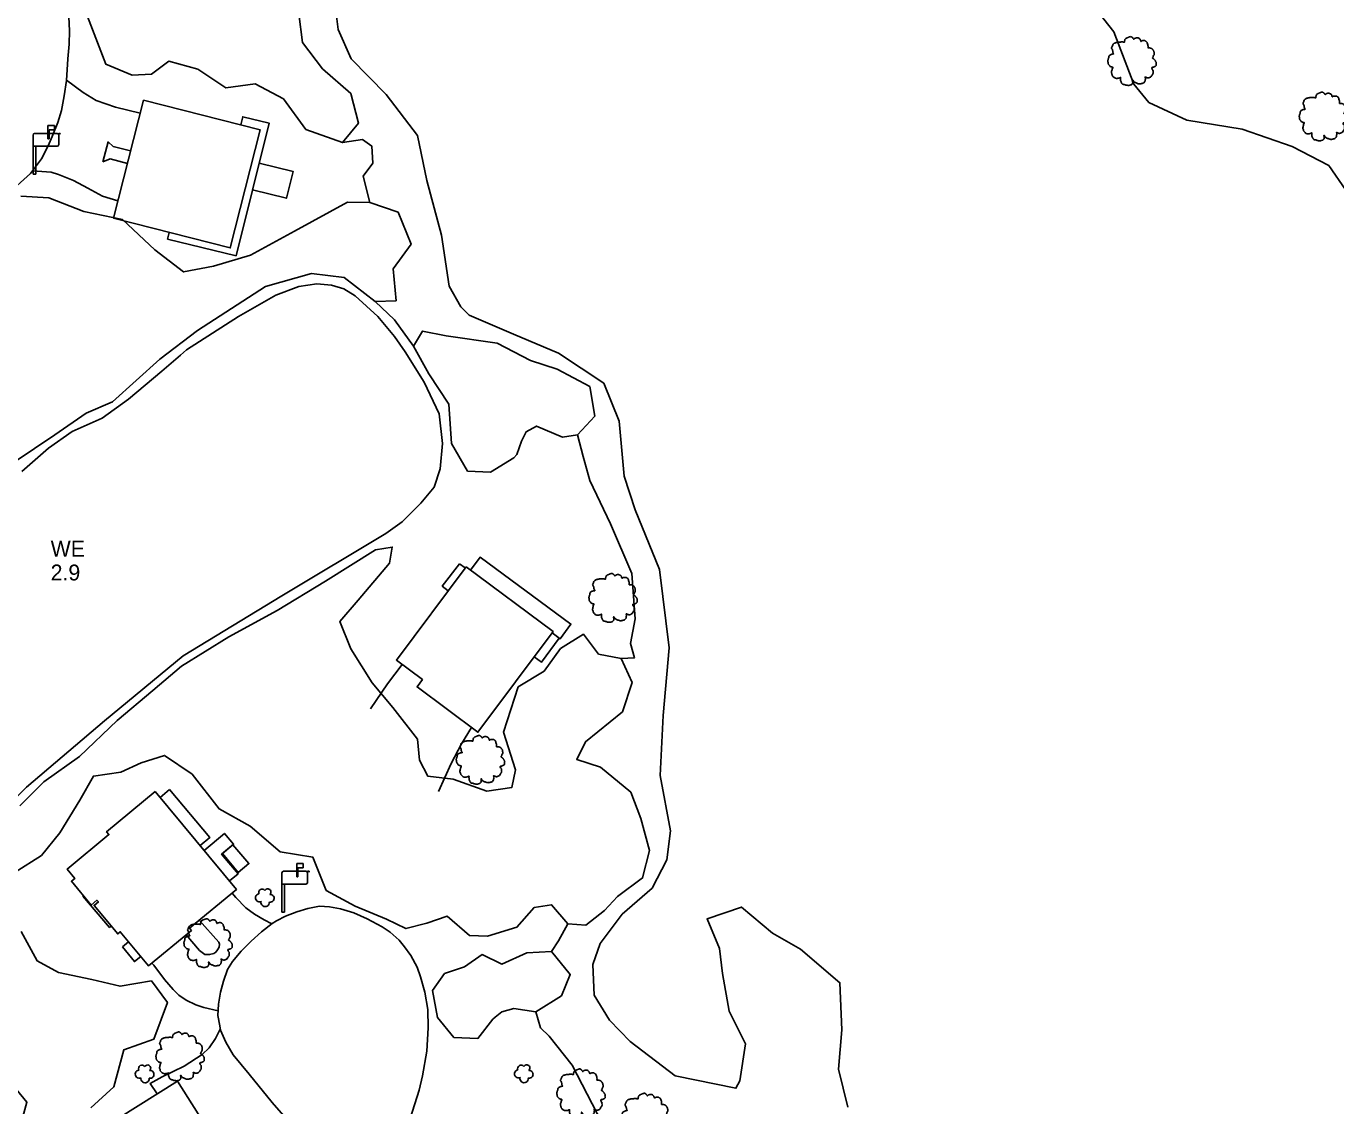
# Model space of a CAD drawing. Extents: x 2160437 to 2172832, y 205694 to 212444.
# Drawn here: x 2171600 to 2172011.7, y 207128.5 to 207468 of the extents above; entities that cross this region are included whole.
import ezdxf

# ---------------------------------------------------------------- set-up
doc = ezdxf.new("R2010")
doc.units = 0
for name, color, linetype in [('RD_EX_Bldg', 7, 'Continuous'), ('RD_EX_Bldg_Walls', 7, 'Continuous'), ('RD_EX_BldgApp', 7, 'Continuous'), ('RD_EX_Driveway', 7, 'Continuous'), ('RD_EX_H2O_Pond', 7, 'Continuous'), ('RD_EX_H2O_txCode', 7, 'Continuous'), ('RD_EX_Road', 7, 'Continuous'), ('RD_EX_VEG', 7, 'Continuous'), ('RD_EX_VEG_ShrubLine', 7, 'Continuous'), ('RD_EX_VEG_TreeLine', 7, 'Continuous')]:
    doc.layers.add(name, color=color, linetype=linetype)

# ---------------------------------------------------------------- blocks, each defined once
blk = doc.blocks.new('T2')
at = {"layer": 'RD_EX_VEG'}
for points in [[(0.05, 7.21), (-0.25, 7.24), (-0.57, 7.14), (-0.82, 7.04), (-1.05, 6.96), (-1.27, 6.86), (-1.57, 6.69), (-1.8, 6.49), (-1.92, 6.24), (-1.97, 6.01), (-2.02, 5.74), (-2.02, 5.56), (-2.15, 5.54), (-2.3, 5.56), (-2.55, 5.64), (-2.8, 5.64), (-3.05, 5.64), (-3.4, 5.61), (-3.75, 5.61), (-4.02, 5.56), (-4.35, 5.51), (-4.72, 5.39), (-5.07, 5.26), (-5.37, 5.01), (-5.62, 4.54), (-5.75, 4.19), (-5.9, 3.94), (-5.75, 3.49), (-5.57, 3.14), (-5.55, 2.94), (-5.47, 2.52), (-5.37, 2.29), (-5.25, 2.09), (-5.32, 2.07), (-5.7, 2.02), (-6, 1.92), (-6.42, 1.69), (-6.64, 1.47), (-6.74, 1.14), (-6.77, 0.79), (-6.87, 0.59), (-6.94, 0.32), (-6.97, 0.24), (-7.02, -0.08), (-6.92, -0.53), (-6.89, -0.88), (-6.77, -1.11), (-6.62, -1.28), (-6.44, -1.53), (-6.05, -1.76), (-5.72, -1.86), (-5.52, -1.88), (-5.7, -2.38), (-5.75, -2.73), (-5.87, -3.13), (-5.87, -3.21), (-5.92, -3.68), (-5.77, -4.01), (-5.7, -4.38), (-5.52, -4.61), (-5.25, -4.91), (-4.92, -5.13), (-4.42, -5.26), (-4.02, -5.23), (-3.45, -5.06), (-3.2, -4.98), (-3.22, -5.16), (-3.2, -5.53), (-3.2, -5.96), (-3.05, -6.28), (-2.95, -6.56), (-2.8, -6.81), (-2.47, -7.03), (-2.07, -7.11), (-1.65, -7.26), (-1.2, -7.33), (-0.7, -7.36), (-0.1, -7.21), (0.18, -7.08), (0.28, -6.91), (0.48, -6.53), (0.43, -6.31), (0.45, -5.71), (0.55, -5.88), (0.73, -6.23), (1.23, -6.53), (1.63, -6.71), (2.1, -6.86), (2.4, -6.93), (2.88, -6.86), (3.25, -6.78), (3.63, -6.66), (3.93, -6.38), (4.1, -6.11), (4.15, -5.83), (4.23, -5.46), (4.28, -5.28)], [(4.28, -5.28), (4.2, -5.11), (4.15, -4.86), (4.23, -4.88), (4.4, -4.93), (4.68, -5.06), (4.9, -5.13), (5.23, -5.11), (5.5, -5.01), (5.95, -4.73), (6.22, -4.26), (6.5, -3.86), (6.57, -3.53), (6.52, -3.31), (6.5, -2.81), (6.3, -2.56), (6.25, -2.43), (6.15, -2.03), (6.22, -1.98), (6.5, -1.93), (6.87, -1.81), (7.15, -1.68), (7.37, -1.51), (7.45, -1.28), (7.42, -0.88), (7.47, -0.48), (7.4, -0.33), (7.3, -0.18), (7.22, 0.02), (7.07, 0.17), (6.97, 0.32), (6.87, 0.42), (6.75, 0.57), (6.57, 0.69), (6.42, 0.74), (6.37, 0.89), (6.52, 1.09), (6.57, 1.19), (6.6, 1.42), (6.82, 1.77), (6.87, 2.17), (6.82, 2.59), (6.77, 2.87), (6.62, 3.14), (6.42, 3.39), (6.3, 3.56), (6.12, 3.69), (5.8, 3.81), (5.55, 3.86), (5.2, 3.86), (5, 3.91), (5.03, 3.96), (5.03, 4.11), (5.03, 4.39), (4.95, 4.84), (4.8, 5.34), (4.8, 5.36), (4.7, 5.61), (4.48, 5.81), (4.3, 5.91), (4.1, 6.04), (3.85, 6.06), (3.55, 6.06), (3.28, 6.01), (3.08, 5.91), (2.9, 5.79), (2.83, 5.94), (2.73, 6.24), (2.68, 6.39), (2.53, 6.56), (2.3, 6.76), (1.85, 6.89), (1.23, 6.81), (0.93, 6.61), (0.78, 6.44), (0.73, 6.56), (0.53, 6.76), (0.43, 6.94), (0.25, 7.06), (0.1, 7.16), (0, 7.21)]]:
    blk.add_spline(points, degree=3, dxfattribs=at)

msp = doc.modelspace()

# ---------------------------------------------------------------- linework, layer by layer
at = {"layer": 'RD_EX_Bldg'}
for points in [[(2171636.87, 207444.73), (2171673.58, 207435.37), (2171664.13, 207398.29), (2171627.42, 207407.64)], [(2171738.28, 207298.03), (2171765.61, 207277.63), (2171742, 207245.99), (2171722.88, 207260.25), (2171724.57, 207262.53), (2171716.36, 207268.66)], [(2171640.57, 207227.33), (2171666.07, 207196.55), (2171651.34, 207184.35), (2171651.92, 207183.65), (2171638.45, 207172.49), (2171629.54, 207183.25), (2171628.74, 207182.58), (2171621.35, 207191.5), (2171622.67, 207192.6), (2171622.24, 207193.12), (2171620.42, 207191.61), (2171614.21, 207199.1), (2171615.32, 207200.01), (2171612.88, 207202.96), (2171625.99, 207213.81), (2171625.28, 207214.67)], [(2171647.59, 207136.3), (2171665, 207108.58), (2171634.09, 207089.16), (2171616.67, 207116.87)]]:
    msp.add_lwpolyline(points, close=True, dxfattribs=at)
at = {"layer": 'RD_EX_Bldg_Walls'}
for points in [[(2171736.25, 207298.97), (2171730.77, 207291.93), (2171732.64, 207290.47)], [(2171737.98, 207297.63), (2171736.25, 207298.97)], [(2171617.96, 207194.57), (2171617.8, 207194.44)], [(2171617.8, 207194.44), (2171626.2, 207184.6), (2171626.71, 207185.03)], [(2171632.16, 207180.09), (2171630.21, 207178.49)], [(2171630.21, 207178.49), (2171634.01, 207173.85), (2171635.99, 207175.47)]]:
    msp.add_lwpolyline(points, dxfattribs=at)
at = {"layer": 'RD_EX_BldgApp'}
for p, q in [((2171606.78, 207436.74), (2171608.84, 207436.74)), ((2171606.78, 207432.55), (2171606.78, 207436.74)), ((2171608.84, 207435.39), (2171607.16, 207435.39)), ((2171607.16, 207435.39), (2171607.16, 207432.55)), ((2171608.84, 207436.74), (2171608.84, 207435.39)), ((2171602.14, 207430.26), (2171602.14, 207433.76)), ((2171602.64, 207434.26), (2171609.71, 207434.26)), ((2171607.16, 207432.55), (2171606.78, 207432.55)), ((2171610.21, 207433.76), (2171610.21, 207434.26)), ((2171610.21, 207434.26), (2171610.71, 207434.26)), ((2171610.21, 207433.76), (2171610.21, 207430.76)), ((2171610.71, 207434.26), (2171610.71, 207434.01)), ((2171602.14, 207430.26), (2171602.14, 207421.44)), ((2171609.71, 207430.26), (2171602.14, 207430.26)), ((2171602.98, 207430.26), (2171602.98, 207421.44)), ((2171602.14, 207421.44), (2171602.98, 207421.44)), ((2171685.02, 207204.73), (2171687.08, 207204.73)), ((2171685.02, 207200.54), (2171685.02, 207204.73)), ((2171687.08, 207204.73), (2171687.08, 207203.38)), ((2171680.38, 207198.25), (2171680.38, 207201.75)), ((2171680.88, 207202.25), (2171687.95, 207202.25)), ((2171685.4, 207200.54), (2171685.02, 207200.54)), ((2171687.08, 207203.38), (2171685.4, 207203.38)), ((2171685.4, 207203.38), (2171685.4, 207200.54)), ((2171688.45, 207201.75), (2171688.45, 207202.25)), ((2171688.45, 207202.25), (2171688.95, 207202.25)), ((2171688.45, 207201.75), (2171688.45, 207198.75)), ((2171688.95, 207202.25), (2171688.95, 207202)), ((2171680.38, 207198.25), (2171680.38, 207189.43)), ((2171687.95, 207198.25), (2171680.38, 207198.25)), ((2171681.22, 207198.25), (2171681.22, 207189.43)), ((2171680.38, 207189.43), (2171681.22, 207189.43))]:
    msp.add_line(p, q, dxfattribs=at)
for points in [[(2171665.99, 207395.74), (2171676.32, 207437.51), (2171668.09, 207439.54), (2171667.44, 207436.94)], [(2171624.12, 207425.4), (2171625.71, 207431.6), (2171627.36, 207430.16), (2171632.8, 207428.77)], [(2171631.81, 207424.87), (2171626.4, 207426.25), (2171624.12, 207425.4)], [(2171644.97, 207403.17), (2171644.45, 207401.07), (2171665.99, 207395.74)], [(2171765.3, 207277.21), (2171767.84, 207275.34), (2171771.25, 207279.97), (2171742.7, 207300.99), (2171739.72, 207296.95)], [(2171765.3, 207277.21), (2171767.55, 207275.55), (2171761.96, 207267.96), (2171759.66, 207269.65)], [(2171642.09, 207225.49), (2171644.99, 207227.93)], [(2171644.99, 207227.93), (2171657.67, 207212.83), (2171654.67, 207210.31)], [(2171655.92, 207208.8), (2171662.29, 207214.18), (2171665.17, 207210.77), (2171661.43, 207207.61), (2171666.59, 207201.5), (2171663.87, 207199.2)]]:
    msp.add_lwpolyline(points, dxfattribs=at)
for points in [[(2171673.22, 207424.97), (2171671.13, 207416.52), (2171681.81, 207413.88), (2171683.9, 207422.33)], [(2171661.66, 207207.8), (2171664.99, 207210.61), (2171669.99, 207204.69), (2171666.66, 207201.88)]]:
    msp.add_lwpolyline(points, close=True, dxfattribs=at)
for centre, start, end in [((2171602.64, 207433.76), 90, 180), ((2171609.71, 207433.76), 360, 90), ((2171609.71, 207430.76), 270, 0), ((2171680.88, 207201.75), 90, 180), ((2171687.95, 207201.75), 360, 90), ((2171687.95, 207198.75), 270, 0)]:
    msp.add_arc(centre, 0.5, start, end, dxfattribs=at)
at = {"layer": 'RD_EX_Driveway'}
for points in [[(2171612.64, 207451.01), (2171617.85, 207447.11), (2171622.01, 207444.67), (2171628.09, 207442.53), (2171635.83, 207440.66)], [(2171601.96, 207422.51), (2171607.85, 207422.06), (2171610.1, 207421.34), (2171614.88, 207419.53), (2171619.4, 207417.11), (2171623.95, 207414.55), (2171628.81, 207413.11)], [(2171708.26, 207253.35), (2171713.58, 207261.16), (2171718.14, 207267.33)], [(2171729.59, 207227.32), (2171733.57, 207236.17), (2171736.8, 207242.3), (2171740.03, 207247.45)], [(2171677.22, 207185.7), (2171674.75, 207186.96), (2171671.79, 207188.73), (2171669.04, 207190.81), (2171665.88, 207193.99), (2171664.69, 207195.41)], [(2171650.26, 207182.28), (2171654.5, 207177.38), (2171656.15, 207176.1), (2171657.65, 207176.06), (2171658.97, 207176.37), (2171659.61, 207176.84), (2171660.15, 207177.51), (2171660.62, 207178.43), (2171660.71, 207179.38), (2171660.56, 207180.01), (2171654.33, 207186.83)], [(2171660.35, 207158.36), (2171655.87, 207159.45), (2171653.29, 207160.23), (2171650.3, 207161.68), (2171647.92, 207163.31), (2171646.22, 207165.07), (2171643.5, 207168.21), (2171640.11, 207172.71), (2171639.5, 207173.36)], [(2171661, 207152.58), (2171659.54, 207149.64), (2171657.46, 207146.77), (2171655.28, 207144.62), (2171649.66, 207140.96), (2171642.72, 207137.58), (2171638.92, 207135.51), (2171641.17, 207132.27)]]:
    msp.add_lwpolyline(points, dxfattribs=at)
at = {"layer": 'RD_EX_H2O_Pond'}
msp.add_lwpolyline([(2171598.64, 207328.01), (2171607.01, 207335.28), (2171614.48, 207340.58), (2171623.86, 207344.75), (2171632.17, 207350.67), (2171642.6, 207359.54), (2171648.52, 207364.58), (2171650.35, 207366.23), (2171666.71, 207376.73), (2171678.44, 207383.47), (2171685.71, 207386.12), (2171691.33, 207386.98), (2171695.93, 207386.59), (2171699.81, 207385.42), (2171703.45, 207383.19), (2171710.51, 207376.68), (2171715.76, 207370.41), (2171719.11, 207365.57), (2171725.08, 207356.02), (2171729.86, 207346.1), (2171730.84, 207336.76), (2171730.13, 207328.81), (2171728.25, 207323.07), (2171724.08, 207317.98), (2171718.18, 207312.11), (2171713.08, 207308.52), (2171680.39, 207288.92), (2171649.28, 207269.97), (2171624.55, 207249.56), (2171600.08, 207228.72), (2171576.41, 207204.98)], dxfattribs=at)
at = {"layer": 'RD_EX_Road'}
for points in [[(2171593.86, 207414.95), (2171601.3, 207421.64), (2171604.83, 207426.32), (2171606.94, 207430.35), (2171608.16, 207433.34), (2171609.95, 207437.71), (2171611.07, 207441.53), (2171611.93, 207446.11), (2171612.63, 207450.95), (2171613.07, 207457.73), (2171613.46, 207462.37), (2171613.63, 207466.51), (2171613.34, 207470.94)], [(2171720.73, 207124.47), (2171723.58, 207133.37), (2171724.6, 207137.97), (2171725.91, 207145.73), (2171726.36, 207152.99), (2171726.25, 207158.77), (2171725.26, 207164.28), (2171723.92, 207169.11), (2171722.87, 207172.06), (2171720.92, 207175.78), (2171718.97, 207178.5), (2171717.23, 207180.62), (2171714.42, 207183.11), (2171711.89, 207184.8), (2171707.22, 207187.28), (2171702.97, 207189.19), (2171698.79, 207190.48), (2171695.32, 207191.11), (2171692.16, 207191.24), (2171688.51, 207190.54), (2171685.03, 207189.5), (2171681.55, 207188.18), (2171678.68, 207186.63), (2171677.33, 207185.78), (2171673.99, 207183.22), (2171670.75, 207180.32), (2171667.55, 207177.17), (2171664.81, 207173.86), (2171663.31, 207171.33), (2171661.97, 207167.75), (2171661.11, 207164.27), (2171660.47, 207160.5), (2171660.26, 207156.86), (2171660.81, 207153.64), (2171661.04, 207152.31), (2171662.75, 207148.48), (2171665.03, 207144.54), (2171670.09, 207138.42), (2171677.29, 207129.57), (2171684.52, 207121.22)]]:
    msp.add_lwpolyline(points, dxfattribs=at)
at = {"layer": 'RD_EX_VEG'}
for centre, radius, start, end in [((2171674.15, 207195.6), 1.08, 34.9763, 204.756), ((2171675.92, 207195.75), 0.995, 308.7626, 152.0467), ((2171673.31, 207193.89), 1.26, 96.4518, 294.734), ((2171675.12, 207192.45), 1.32, 166.8827, 5.7589), ((2171676.71, 207193.77), 1.22, 256.5667, 98.1046), ((2171635.54, 207138.49), 1.26, 96.4518, 294.734), ((2171636.38, 207140.2), 1.08, 34.9763, 204.756), ((2171638.15, 207140.35), 0.995, 308.7626, 152.0467), ((2171638.94, 207138.37), 1.22, 256.5667, 98.1046), ((2171754.73, 207138.53), 1.26, 96.4518, 294.734), ((2171755.57, 207140.24), 1.08, 34.9763, 204.756), ((2171757.34, 207140.39), 0.995, 308.7626, 152.0467), ((2171758.13, 207138.41), 1.22, 256.5667, 98.1046), ((2171637.35, 207137.05), 1.32, 166.8827, 5.7589), ((2171756.54, 207137.09), 1.32, 166.8827, 5.7589)]:
    msp.add_arc(centre, radius, start, end, dxfattribs=at)
at = {"layer": 'RD_EX_VEG_ShrubLine'}
for points in [[(2171696.47, 207479.68), (2171698.1, 207466.96), (2171702.18, 207457.7), (2171713.19, 207446.54), (2171722.96, 207433.6), (2171725.98, 207419.49), (2171730.58, 207402.3), (2171733.01, 207386.21), (2171736.66, 207379.72), (2171739.22, 207377.16), (2171753.23, 207371.14), (2171767.29, 207365.2), (2171781.63, 207355.72), (2171786.41, 207343.79), (2171787.97, 207326.5), (2171791.44, 207315.92), (2171799.05, 207297.13), (2171802.15, 207272.5), (2171800.28, 207251.23), (2171799.28, 207232.34), (2171802.54, 207215.02), (2171801.4, 207205.81), (2171796.78, 207196.93), (2171787.36, 207188.75), (2171780.44, 207179.53), (2171778.18, 207172.98), (2171778.53, 207163.3), (2171783.35, 207155.42), (2171789.87, 207148.68), (2171804.04, 207137.88), (2171823.12, 207134.02), (2171824.39, 207136.33), (2171826.14, 207148.03), (2171821.03, 207158.29), (2171818.86, 207170.09), (2171818, 207177.97), (2171814.04, 207187.27), (2171824.83, 207190.97), (2171834.66, 207182.81), (2171843.43, 207177.71), (2171855.81, 207167.2), (2171856.38, 207152.4), (2171855.39, 207140.03), (2171858.34, 207128.08)], [(2172020.2, 207408.68), (2172009.49, 207424.2), (2171998.04, 207430.21), (2171982.26, 207435.66), (2171964.92, 207438.4), (2171952.96, 207444.01), (2171948.25, 207449.81), (2171941.89, 207466.2), (2171935.23, 207474.72)], [(2171708.06, 207412.6), (2171705.88, 207420.87), (2171709.01, 207424.88), (2171708.62, 207430.3), (2171705.73, 207432.38), (2171699.44, 207431.39)], [(2171721.8, 207367.43), (2171715.75, 207375.67), (2171709.69, 207381.48)], [(2171787.04, 207269.15), (2171791.2, 207269.37), (2171789.97, 207273.9), (2171791.41, 207281.68), (2171790.34, 207295.86), (2171783.66, 207311.55), (2171777.18, 207325.11), (2171775.11, 207332.69), (2171773.29, 207339.46)], [(2171765.16, 207177.03), (2171767.35, 207180.4), (2171770.32, 207185.73)], [(2171726.2, 207052.3), (2171735.67, 207064.74), (2171740.4, 207075.71), (2171744.57, 207088.97), (2171748.02, 207096.69), (2171753.17, 207101.16), (2171763.2, 207104.14), (2171769.13, 207102.37), (2171779.06, 207098.87), (2171781.92, 207115.3), (2171781.1, 207123.06), (2171771.64, 207141.31), (2171764.4, 207150.42), (2171761.66, 207153.06), (2171760.17, 207158.05)]]:
    msp.add_lwpolyline(points, dxfattribs=at)
at = {"layer": 'RD_EX_VEG_TreeLine'}
for points in [[(2171685.66, 207471.86), (2171686.9, 207462.86), (2171693.16, 207454.6), (2171702.08, 207446.83), (2171704.41, 207437.54), (2171699.44, 207431.39), (2171687.92, 207435.48), (2171680.87, 207445.11), (2171672.01, 207449.9), (2171662.76, 207448.57), (2171653.9, 207454.48), (2171644.81, 207457.03), (2171639.37, 207452.93), (2171633.32, 207452.57), (2171624.99, 207456.1), (2171618.76, 207472.37)], [(2171598.26, 207414.57), (2171607.07, 207414.07), (2171618.15, 207409.68), (2171630.21, 207407.18), (2171640.46, 207397.69), (2171649.44, 207390.71), (2171658.84, 207392.58), (2171670.45, 207395.98), (2171684.29, 207403.53), (2171701, 207412.7), (2171708.06, 207412.6), (2171716.92, 207409.54), (2171721, 207399.43), (2171715.39, 207391.65), (2171716.29, 207381.69), (2171709.69, 207381.48), (2171699.95, 207389), (2171689.67, 207390.28), (2171675.27, 207386.14), (2171653.8, 207372.36), (2171641.99, 207363.26), (2171627.11, 207349.9), (2171618.85, 207346.28), (2171609.03, 207339.53), (2171596.22, 207330.89)], [(2171597.95, 207222.87), (2171605.48, 207230.42), (2171616.74, 207238.39), (2171628.55, 207249.63), (2171639.84, 207259.08), (2171648.81, 207266.72), (2171663.67, 207276.02), (2171678.92, 207284.3), (2171694.06, 207293.46), (2171709.82, 207303.31), (2171715.05, 207304.22), (2171714.22, 207299.15), (2171704.38, 207287.53), (2171698.6, 207280.78), (2171702.01, 207272.16), (2171708.74, 207261.49), (2171715.24, 207253.79), (2171723.04, 207243.77), (2171723.68, 207237.17), (2171726.27, 207232.13), (2171734.21, 207231.25), (2171744.76, 207227.47), (2171752.64, 207228.55), (2171753.85, 207234.19), (2171750.07, 207245.98), (2171754.7, 207260.21), (2171762.88, 207265.21), (2171767.95, 207272.29), (2171775.15, 207276.78), (2171779.96, 207270.5), (2171787.04, 207269.15), (2171790.5, 207261.62), (2171787.47, 207252.43), (2171775.8, 207242.96), (2171773.07, 207237.36), (2171780.54, 207235), (2171790.03, 207227.13), (2171793.27, 207218.9), (2171795.99, 207208.77), (2171793.75, 207200.18), (2171785.9, 207194.28), (2171781.78, 207189.97), (2171775.98, 207185.26), (2171770.32, 207185.73), (2171765.17, 207191.74), (2171759.68, 207190.82), (2171754.27, 207184.65), (2171744.97, 207181.87), (2171739.33, 207182.01), (2171732.38, 207188.09), (2171725.93, 207185.93), (2171719.39, 207184.25), (2171713.23, 207187.19), (2171703.45, 207191.26), (2171703.45, 207191.26), (2171694.29, 207196.23), (2171690.13, 207206.69), (2171679.78, 207208.36), (2171670.43, 207216.4), (2171660.62, 207221.88), (2171652.16, 207232.78), (2171643.51, 207238.71), (2171636.11, 207236.38), (2171629.71, 207233.44), (2171621.11, 207232.17), (2171616.88, 207224.6), (2171610.53, 207214.33), (2171604.83, 207207.24), (2171596.52, 207201.97)], [(2171598.4, 207183.32), (2171603.44, 207174.05), (2171610.11, 207170.44), (2171620.62, 207168.18), (2171629.51, 207166.12), (2171639.36, 207167.79), (2171644.36, 207160.99), (2171640.13, 207149.47), (2171630.68, 207146.12), (2171627.58, 207134.5), (2171620.31, 207127.91)], [(2171598.12, 207122.01), (2171600.22, 207129.6), (2171600.22, 207129.6), (2171596.78, 207133.75)]]:
    msp.add_lwpolyline(points, dxfattribs=at)
for points in [[(2171753.32, 207332.29), (2171745.99, 207327.75), (2171738.76, 207328.08), (2171733.66, 207336.74), (2171732.86, 207349.19), (2171726.52, 207358.63), (2171721.8, 207367.43), (2171724.6, 207372.13), (2171732.04, 207370.63), (2171748.06, 207368.28), (2171758.5, 207362.84), (2171766.88, 207360.16), (2171777.19, 207354.67), (2171778.79, 207345.38), (2171773.29, 207339.46), (2171768.58, 207338.74), (2171760.47, 207342.26), (2171757.18, 207340.46), (2171755.71, 207337.5), (2171754.2, 207333.28)], [(2171746.72, 207155.79), (2171742.01, 207149.72), (2171734.44, 207150), (2171729.32, 207156.31), (2171727.75, 207164.73), (2171731.52, 207170.16), (2171737.8, 207172.19), (2171743.33, 207176.06), (2171749.51, 207173), (2171757.39, 207176.65), (2171765.16, 207177.03), (2171771.04, 207169.83), (2171768.26, 207163.09), (2171760.17, 207158.05), (2171753.27, 207159.09), (2171749.56, 207158.01), (2171747.44, 207156.42)]]:
    msp.add_lwpolyline(points, close=True, dxfattribs=at)

# ---------------------------------------------------------------- block references
at = {"layer": 'RD_EX_VEG', "xscale": 1.0499999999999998, "yscale": 1.0499999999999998}
for p in [(2171947.4, 207457.11), (2172007.59, 207439.68), (2171784.26, 207288.31), (2171742.57, 207237.38), (2171656.92, 207179.74), (2171648.13, 207144.12), (2171774.16, 207132.5), (2171794.48, 207124.85)]:
    msp.add_blockref('T2', p, dxfattribs=at)

# ---------------------------------------------------------------- texts
at = {"layer": 'RD_EX_H2O_txCode'}
for s, p in [('WE', (2171607.68, 207301.21)), ('2.9', (2171607.68, 207293.71))]:
    msp.add_text(s, height=5, dxfattribs=at).set_placement(p)

doc.saveas('drawing.dxf')
